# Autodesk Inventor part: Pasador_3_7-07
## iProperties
Company: COMGRAP
Created: 2008-01
Part Number: Pasador_3_7-07
Document SubType Name: Modeling
Designer: eruiz-tagle
Density: 1.06 g/cm^3
Mass: 0.249535 g
Surface Area: 3.24985 cm^2
Volume: 0.235411 cm^3
Material: ABS Plastic
Author: Esteban
Title: CURSO INVENTOR
Comments: Esta pieza fue creada en el curso de inventor
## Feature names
1. Extrusion1
2. Fillet1
3. Revolution1
4. Mirror1
